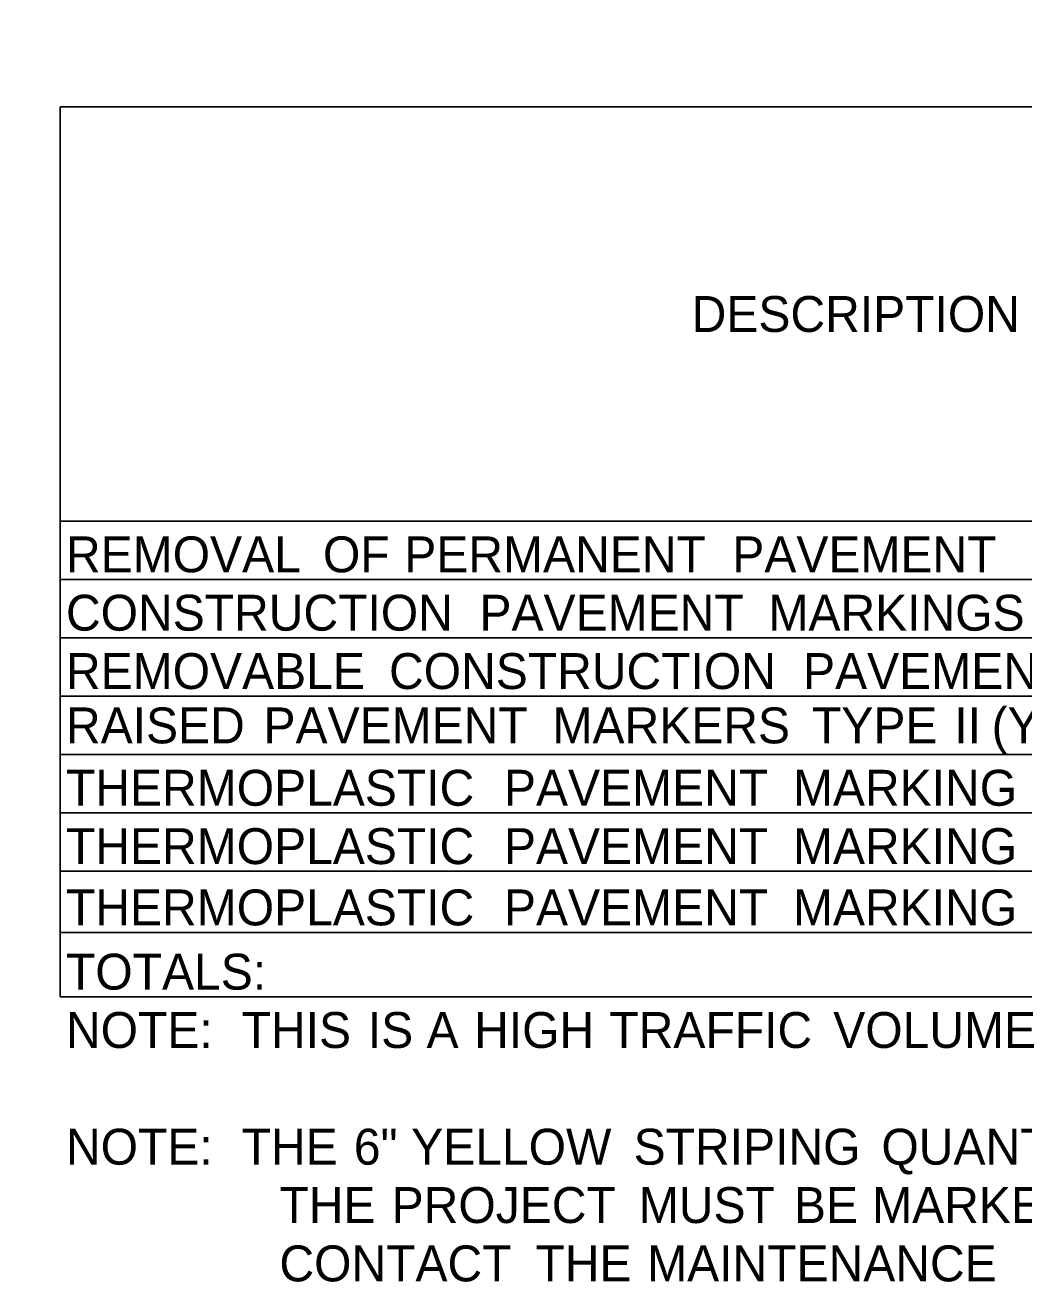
# Model space of a CAD drawing. Extents: x 1197542 to 1207068, y 230488 to 237324.
# Drawn here: x 1197910.2 to 1198077.1, y 231853.1 to 232063.1 of the extents above; entities that cross this region are included whole.
import ezdxf

# ---------------------------------------------------------------- set-up
doc = ezdxf.new("R2010")
doc.units = 0
doc.layers.add('Default', color=7, linetype='Continuous')

msp = doc.modelspace()

# ---------------------------------------------------------------- linework, layer by layer
at = {"layer": 'Default'}
for p, q in [((1197910.22, 232063.11), (1197910.22, 232063.11)), ((1197916.07, 232049.46), (1198799.9, 232049.46)), ((1197916.07, 231900.77), (1197916.07, 232049.46)), ((1197916.07, 231900.77), (1197916.07, 232049.46)), ((1197916.07, 231980.24), (1198799.9, 231980.24)), ((1197916.07, 231970.49), (1198799.9, 231970.49)), ((1197916.07, 231960.74), (1198799.9, 231960.74)), ((1197916.07, 231950.99), (1198799.9, 231950.99)), ((1197916.07, 231941.24), (1198799.9, 231941.24)), ((1197916.07, 231931.49), (1198799.9, 231931.49)), ((1197916.07, 231921.74), (1198799.9, 231921.74)), ((1197916.07, 231911.5), (1198799.9, 231911.5)), ((1197916.07, 231911.5), (1198334.34, 231911.5)), ((1197916.07, 231900.77), (1198799.9, 231900.77))]:
    msp.add_line(p, q, dxfattribs=at)

# ---------------------------------------------------------------- texts
for s, p in [('DESCRIPTION', (1198021.57, 232011.85)), ('REMOVAL', (1197917.04, 231971.69)), (' OF', (1197957.74, 231971.69)), (' PERMANENT', (1197971.33, 231971.69)), (' PAVEMENT', (1198026.13, 231971.69)), ('CONSTRUCTION', (1197917.04, 231961.94)), (' PAVEMENT', (1197983.89, 231961.94)), (' MARKINGS', (1198032.17, 231961.94)), ('REMOVABLE', (1197917.04, 231952.19)), (' CONSTRUCTION', (1197968.78, 231952.19)), (' PAVEMENT', (1198037.95, 231952.19)), ('RAISED', (1197917.04, 231943.11)), (' PAVEMENT', (1197947.81, 231943.11)), (' MARKERS', (1197996.09, 231943.11)), (' TYPE', (1198039.45, 231943.11)), (' II', (1198063.23, 231943.11)), (' (YEL/YEL)', (1198069.46, 231943.11)), ('THERMOPLASTIC', (1197917.04, 231932.69)), (' PAVEMENT', (1197987.98, 231932.69)), (' MARKING', (1198036.26, 231932.69)), ('THERMOPLASTIC', (1197917.04, 231922.94)), (' PAVEMENT', (1197987.98, 231922.94)), (' MARKING', (1198036.26, 231922.94)), ('THERMOPLASTIC', (1197917.04, 231912.7)), (' PAVEMENT', (1197987.98, 231912.7)), (' MARKING', (1198036.26, 231912.7)), ('TOTALS:', (1197917.04, 231901.97)), ('NOTE:', (1197917.04, 231892.22)), ('  THIS', (1197941.93, 231892.22)), (' IS', (1197965.24, 231892.22)), (' A', (1197975.05, 231892.22)), (' HIGH', (1197982.99, 231892.22)), (' TRAFFIC', (1198005.59, 231892.22)), (' VOLUME', (1198042.99, 231892.22)), ('NOTE:', (1197917.04, 231872.72)), ('  THE', (1197941.93, 231872.72)), (' 6"', (1197962.9, 231872.72)), (' YELLOW', (1197972.48, 231872.72)), (' STRIPING', (1198009.65, 231872.72)), (' QUANTITY', (1198051.04, 231872.72)), ('  THE', (1197948.24, 231862.97)), (' PROJECT', (1197969.22, 231862.97)), (' MUST', (1198010.51, 231862.97)), (' BE', (1198036.42, 231862.97)), (' MARKED', (1198049.49, 231862.97)), ('  CONTACT', (1197948.24, 231853.22)), (' THE', (1197993.25, 231853.22)), (' MAINTENANCE', (1198011.9, 231853.22))]:
    msp.add_text(s, height=6, dxfattribs=at).set_placement(p)

doc.saveas('drawing.dxf')
